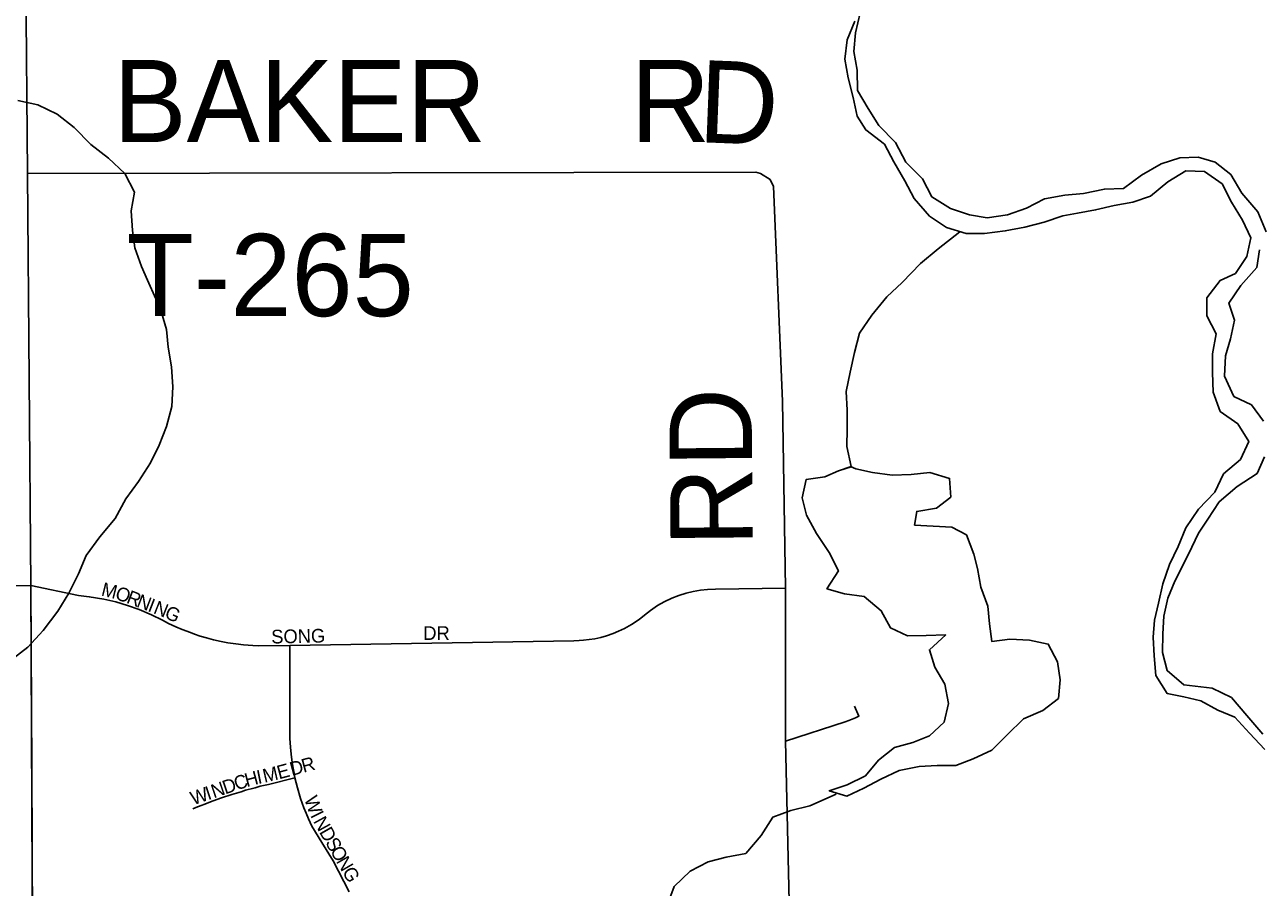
# Model space of a CAD drawing. Extents: x 1985906 to 2277390, y 930619 to 1324581.
# Drawn here: x 2139705 to 2144205, y 1158270 to 1161418 of the extents above; entities that cross this region are included whole.
import ezdxf

# ---------------------------------------------------------------- set-up
doc = ezdxf.new("R2010")
doc.units = 0
for name, color, linetype in [('GM_X_County_Road', 7, 'Continuous'), ('GM_X_Major_River', 7, 'Continuous'), ('GM_X_Minor_Lake', 7, 'Continuous'), ('GM_X_Minor_River', 7, 'Continuous'), ('GM_X_Township', 7, 'Continuous'), ('GM_X_Township_Road', 7, 'Continuous'), ('GM_X_Township_Road_Text', 7, 'Continuous'), ('GM_X_Township_Subdivision', 7, 'Continuous'), ('GM_X_Township_Subdivision_Text', 7, 'Continuous')]:
    doc.layers.add(name, color=color, linetype=linetype)

msp = doc.modelspace()

# ---------------------------------------------------------------- linework, layer by layer
at = {"layer": 'GM_X_County_Road'}
for points in [[(2139728.2, 1159371.8), (2139715.7, 1160875.4), (2139697.8, 1163007), (2139679.7, 1165170.7)], [(2139731.2, 1158704.9), (2139728.2, 1159371.8)], [(2139737.6, 1157268.3), (2139731.2, 1158704.9)]]:
    msp.add_lwpolyline(points, dxfattribs=at)
at = {"layer": 'GM_X_Major_River'}
for points in [[(2144233.2, 1160662.6), (2144203.2, 1160734.7), (2144145.1, 1160802.8), (2144105.1, 1160870.9), (2144047, 1160916.9), (2143985.1, 1160934.9), (2143919.1, 1160932.8), (2143851.1, 1160910.7), (2143779.2, 1160868.6), (2143713.3, 1160820.4), (2143643.3, 1160818.4), (2143567.3, 1160802.3), (2143499.4, 1160796.2), (2143425.4, 1160782.1), (2143359.5, 1160748), (2143289.5, 1160723.9), (2143215.6, 1160713.8), (2143151.6, 1160723.7), (2143081.6, 1160747.7), (2143013.6, 1160789.7), (2142979.5, 1160855.8), (2142919.5, 1160915.9), (2142881.4, 1160988), (2142821.4, 1161050), (2142781.4, 1161112.1), (2142743.3, 1161178.2), (2142741.2, 1161252.3), (2142729.2, 1161320.4), (2142735.1, 1161388.6), (2142753, 1161460.7)], [(2142733.1, 1161430.6), (2142705.1, 1161362.5), (2142697.2, 1161292.4), (2142709.3, 1161224.2), (2142727.3, 1161152.1), (2142741.4, 1161084), (2142773.4, 1161034), (2142841.5, 1160981.9), (2142875.5, 1160917.8), (2142915.6, 1160847.7), (2142949.6, 1160783.6), (2143005.7, 1160719.6), (2143067.7, 1160677.6), (2143139.7, 1160655.6), (2143205.6, 1160655.6), (2143281.6, 1160665.7), (2143353.5, 1160679.8), (2143423.5, 1160697.9), (2143491.5, 1160720), (2143545.4, 1160730.1), (2143611.4, 1160742.2), (2143679.3, 1160758.3), (2143747.3, 1160770.4), (2143811.3, 1160792.5), (2143875.2, 1160844.6), (2143941.1, 1160884.8), (2144009.1, 1160882.8), (2144073.1, 1160836.8), (2144107.2, 1160770.7), (2144147.2, 1160704.6), (2144177.3, 1160640.5), (2144163.3, 1160572.4), (2144121.4, 1160510.2), (2144065.5, 1160484.1), (2144017.5, 1160422), (2144017.6, 1160355.8), (2144051.6, 1160289.8), (2144037.7, 1160217.6), (2144037.8, 1160149.5), (2144039.9, 1160077.3), (2144065.9, 1160007.2), (2144129.9, 1159961.2), (2144170, 1159897.1), (2144140, 1159831)], [(2142733.1, 1161430.6), (2142705.1, 1161362.5), (2142697.2, 1161292.4), (2142709.3, 1161224.2), (2142727.3, 1161152.1), (2142741.4, 1161084), (2142773.4, 1161034), (2142841.5, 1160981.9), (2142875.5, 1160917.8), (2142915.6, 1160847.7), (2142949.6, 1160783.6), (2143005.7, 1160719.6), (2143067.7, 1160677.6), (2143139.7, 1160655.6), (2143205.6, 1160655.6), (2143281.6, 1160665.7), (2143353.5, 1160679.8), (2143423.5, 1160697.9), (2143491.5, 1160720), (2143545.4, 1160730.1), (2143611.4, 1160742.2), (2143679.3, 1160758.3), (2143747.3, 1160770.4), (2143811.3, 1160792.5), (2143875.2, 1160844.6), (2143941.1, 1160884.8), (2144009.1, 1160882.8), (2144073.1, 1160836.8), (2144107.2, 1160770.7), (2144147.2, 1160704.6), (2144177.3, 1160640.5), (2144163.3, 1160572.4), (2144121.4, 1160510.2), (2144065.5, 1160484.1), (2144017.5, 1160422), (2144017.6, 1160355.8), (2144051.6, 1160289.8), (2144037.7, 1160217.6), (2144037.8, 1160149.5), (2144039.9, 1160077.3), (2144065.9, 1160007.2), (2144129.9, 1159961.2), (2144170, 1159897.1), (2144140, 1159831)], [(2144223.9, 1159971.3), (2144179.8, 1160031.4), (2144115.8, 1160061.4), (2144081.8, 1160135.5), (2144085.7, 1160209.6), (2144103.6, 1160271.8), (2144117.6, 1160339.9), (2144097.5, 1160402), (2144141.4, 1160466.1), (2144199.4, 1160532.3), (2144209.3, 1160596.5)], [(2144140, 1159831), (2144078.1, 1159778.8), (2144046.2, 1159712.6), (2143986.3, 1159650.5), (2143940.4, 1159582.3), (2143912.4, 1159514.1), (2143880.5, 1159448), (2143856.6, 1159377.8), (2143840.7, 1159307.7), (2143826.7, 1159245.6), (2143820.8, 1159183.4), (2143824.8, 1159115.3), (2143830.9, 1159043.2), (2143873, 1158977.1), (2143933, 1158965.1), (2143994.9, 1158951.1), (2144056.9, 1158917.1), (2144118.9, 1158891.1), (2144173, 1158833.1), (2144229, 1158773)], [(2144221, 1158829.1), (2144162.9, 1158897.2), (2144106.9, 1158963.3), (2144036.9, 1158997.3), (2143932.9, 1159009.2), (2143872.9, 1159061.2), (2143854.8, 1159127.4), (2143856.8, 1159195.5), (2143860.7, 1159259.6), (2143874.6, 1159325.8), (2143900.6, 1159387.9), (2143932.5, 1159450.1), (2143962.4, 1159512.2), (2143986.4, 1159562.3), (2144020.3, 1159614.4), (2144062.2, 1159676.6), (2144128.1, 1159732.8), (2144200.1, 1159780.9), (2144228, 1159841.1)]]:
    msp.add_lwpolyline(points, dxfattribs=at)
at = {"layer": 'GM_X_Minor_Lake'}
for points in [[(2142720.1, 1159805.4), (2142674.3, 1159789.8), (2142623.4, 1159768.3), (2142555.5, 1159758.3), (2142541.5, 1159692.2), (2142557.5, 1159628.1), (2142593.5, 1159562), (2142639.5, 1159491.9), (2142673.5, 1159425.8), (2142631.6, 1159359.7), (2142695.5, 1159341.7), (2142767.4, 1159331.7), (2142829.4, 1159279.7), (2142863.3, 1159217.6), (2142925.3, 1159187.6), (2142993.2, 1159189.6), (2143065.1, 1159191.7), (2143005.2, 1159137.6), (2143025.2, 1159073.5), (2143061.2, 1159011.4), (2143075.2, 1158941.3), (2143059.2, 1158873.2), (2143005.3, 1158823.1), (2142945.4, 1158799), (2142877.5, 1158780.9), (2142819.6, 1158734.8), (2142771.7, 1158676.7), (2142705.8, 1158644.6), (2142639.9, 1158622.6), (2142703.8, 1158602.6), (2142765.7, 1158632.6), (2142827.6, 1158664.7)], [(2142719.7, 1159805.3), (2142674.3, 1159789.8), (2142623.4, 1159768.3), (2142555.5, 1159758.3), (2142541.5, 1159692.2), (2142557.5, 1159628.1), (2142593.5, 1159562), (2142639.5, 1159491.9), (2142673.5, 1159425.8), (2142631.6, 1159359.7), (2142695.5, 1159341.7), (2142767.4, 1159331.7), (2142829.4, 1159279.7), (2142863.3, 1159217.6), (2142925.3, 1159187.6), (2142993.2, 1159189.6), (2143065.1, 1159191.7), (2143005.2, 1159137.6), (2143025.2, 1159073.5), (2143061.2, 1159011.4), (2143075.2, 1158941.3), (2143059.2, 1158873.2), (2143005.3, 1158823.1), (2142945.4, 1158799), (2142877.5, 1158780.9), (2142819.6, 1158734.8), (2142771.7, 1158676.7), (2142705.8, 1158644.6), (2142639.9, 1158622.6), (2142703.8, 1158602.6), (2142765.7, 1158632.6), (2142827.6, 1158664.7)], [(2142827.6, 1158664.7), (2142895.5, 1158696.8), (2142967.4, 1158710.9), (2143033.3, 1158714.9), (2143101.2, 1158714.9), (2143165.1, 1158739), (2143233, 1158771.1), (2143288.9, 1158827.2), (2143348.8, 1158885.3), (2143418.7, 1158915.4), (2143476.6, 1158959.5), (2143482.6, 1159027.6), (2143472.6, 1159093.7), (2143438.6, 1159157.8), (2143370.7, 1159171.8), (2143298.8, 1159175.8), (2143232.9, 1159167.7), (2143224.9, 1159231.8), (2143218.8, 1159295.9), (2143192.8, 1159366), (2143180.8, 1159434.1), (2143166.8, 1159486.2), (2143140.8, 1159556.3), (2143086.9, 1159584.3), (2142951.1, 1159592.2), (2142959, 1159642.3), (2143030.9, 1159654.4), (2143082.8, 1159694.5), (2143078.8, 1159762.6), (2143006.9, 1159784.6), (2142939, 1159776.5), (2142869.1, 1159774.5), (2142797.2, 1159784.4), (2142736.4, 1159796.9), (2142717.3, 1159806.5)], [(2142827.6, 1158664.7), (2142895.5, 1158696.8), (2142967.4, 1158710.9), (2143033.3, 1158714.9), (2143101.2, 1158714.9), (2143165.1, 1158739), (2143233, 1158771.1), (2143288.9, 1158827.2), (2143348.8, 1158885.3), (2143418.7, 1158915.4), (2143476.6, 1158959.5), (2143482.6, 1159027.6), (2143472.6, 1159093.7), (2143438.6, 1159157.8), (2143370.7, 1159171.8), (2143298.8, 1159175.8), (2143232.9, 1159167.7), (2143224.9, 1159231.8), (2143218.8, 1159295.9), (2143192.8, 1159366), (2143180.8, 1159434.1), (2143166.8, 1159486.2), (2143140.8, 1159556.3), (2143086.9, 1159584.3), (2142951.1, 1159592.2), (2142959, 1159642.3), (2143030.9, 1159654.4), (2143082.8, 1159694.5), (2143078.8, 1159762.6), (2143006.9, 1159784.6), (2142939, 1159776.5), (2142869.1, 1159774.5), (2142797.2, 1159784.4), (2142736.4, 1159796.9), (2142719.7, 1159805.3)]]:
    msp.add_lwpolyline(points, dxfattribs=at)
at = {"layer": 'GM_X_Minor_River'}
for points in [[(2140120.8, 1159750.9), (2140164.6, 1159819.4), (2140196.4, 1159883.7), (2140222.2, 1159952.1), (2140241.9, 1160024.5), (2140245.5, 1160096.8), (2140241.2, 1160169.1), (2140228.8, 1160241.3), (2140222.5, 1160305.5), (2140204.1, 1160367.7), (2140183.8, 1160417.8), (2140153.4, 1160486), (2140131.1, 1160536.1), (2140106.7, 1160604.3), (2140098.4, 1160666.5), (2140094, 1160738.8), (2140105.7, 1160807.1), (2140071.3, 1160875.3), (2140010.9, 1160931.3), (2139946.4, 1160981.3), (2139886, 1161043.3), (2139823.6, 1161091.2), (2139753.2, 1161125.1), (2139680.9, 1161140.9)], [(2143116.2, 1160662.6), (2143037.2, 1160600), (2142972.6, 1160546.4), (2142906.3, 1160476.8), (2142849.6, 1160425.4), (2142795.2, 1160358), (2142750.8, 1160292.9), (2142732.4, 1160222.4), (2142716.1, 1160149.9), (2142701.8, 1160079.4), (2142705.4, 1160011.4), (2142704.9, 1159943.3), (2142704.4, 1159879.2), (2142720.1, 1159805.4)], [(2139652.6, 1159096.6), (2139716.5, 1159147), (2139772.4, 1159207.4), (2139826.2, 1159277.9), (2139866, 1159344.3), (2139901.8, 1159414.8), (2139929.6, 1159481.1), (2139979.4, 1159549.6), (2140035.2, 1159616.1), (2140075, 1159688.5), (2140120.8, 1159750.9)], [(2142664.6, 1158610.7), (2142568.9, 1158567.8), (2142499.4, 1158550.2), (2142434.1, 1158526.7), (2142391.7, 1158459.6), (2142335.3, 1158394.2), (2142263.7, 1158380.5), (2142198.2, 1158362.9), (2142133.1, 1158329.4), (2142074.5, 1158273.9), (2142050, 1158207.2), (2142069.7, 1158135.6), (2142061.3, 1158067.3), (2142050.9, 1157996.9), (2142040.4, 1157932.6), (2142002.1, 1157859.6), (2141973.7, 1157792.8), (2141955.4, 1157722.2), (2141915.1, 1157649.2), (2141878.8, 1157580.2)]]:
    msp.add_lwpolyline(points, dxfattribs=at)
at = {"layer": 'GM_X_Township'}
for points in [[(2139697.8, 1163007), (2139715.7, 1160875.4), (2139728.2, 1159371.8), (2139745, 1155626.5), (2139750.2, 1155246.4), (2139750.9, 1155195.2), (2139750.9, 1154891.9), (2139742.2, 1154437.3), (2139748.3, 1153597.6), (2139771.2, 1150428.8), (2139767.6, 1149880.1), (2139763.4, 1149243.6), (2139772.8, 1148379.5), (2139785.2, 1144742.9), (2139790.1, 1144132.9), (2139795.7, 1143054.9), (2135286.4, 1142976.3)], [(2139771.2, 1150428.8), (2139748.3, 1153597.6), (2139742.2, 1154437.3), (2139750.9, 1154891.9), (2139750.9, 1155195.2), (2139750.2, 1155246.4), (2139745, 1155626.5), (2139728.2, 1159371.8), (2139715.7, 1160875.4), (2139697.8, 1163007)]]:
    msp.add_lwpolyline(points, dxfattribs=at)
at = {"layer": 'GM_X_Township_Road'}
for points in [[(2139715.7, 1160875.4), (2142372.7, 1160879.4), (2142388.7, 1160875.4), (2142424.8, 1160853.5)], [(2142519, 1155650.8), (2142504.6, 1157589.9), (2142495.8, 1158112.1), (2142480.6, 1158803.9), (2142480.6, 1159362.4), (2142469.9, 1160043.8), (2142436.9, 1160827.4), (2142424.8, 1160853.5)], [(2136069.9, 1159324.9), (2137151.4, 1159332.9), (2138108.1, 1159344.7), (2139068.7, 1159359.1), (2139728.2, 1159371.8)]]:
    msp.add_lwpolyline(points, dxfattribs=at)
at = {"layer": 'GM_X_Township_Subdivision'}
for points in [[(2139728.2, 1159371.8), (2139902.2, 1159335.1), (2139941, 1159330.8), (2139994.6, 1159321.7), (2140037.4, 1159311.7), (2140080.5, 1159299.1), (2140123.5, 1159283.7), (2140168.5, 1159264.6), (2140207.8, 1159245.3), (2140230.6, 1159233.5), (2140256.8, 1159221.2), (2140279.3, 1159211.5), (2140309.8, 1159199.7), (2140325.2, 1159194.2), (2140345.9, 1159187.4), (2140369, 1159180.6), (2140394.6, 1159173.9), (2140422.4, 1159167.6), (2140445.9, 1159163.1), (2140475.3, 1159158.5), (2140503.3, 1159155.2), (2140538, 1159152.4), (2140559.8, 1159151.4), (2140672.4, 1159152.5), (2141708.7, 1159170.4), (2141727.9, 1159170.8), (2141744.1, 1159171.9), (2141764.9, 1159174.3), (2141785.1, 1159177.6), (2141806.5, 1159182.4), (2141827.5, 1159188.3), (2141851.9, 1159196.7), (2141871.9, 1159205), (2141892.8, 1159215), (2141918.8, 1159229.7), (2141946.4, 1159248.3), (2141966.3, 1159264), (2141987.8, 1159280.9), (2142013.8, 1159298.3), (2142037.7, 1159312), (2142066.1, 1159325.5), (2142091.3, 1159335.4), (2142117.5, 1159343.6), (2142143.7, 1159349.9), (2142170.8, 1159354.5), (2142195.6, 1159357.1), (2142224.9, 1159358), (2142480.6, 1159362.4)], [(2140888.9, 1158253.8), (2140830.6, 1158367.5), (2140789.4, 1158433.8), (2140753.4, 1158493.1), (2140746.9, 1158506.6), (2140740.8, 1158520.1), (2140732.1, 1158540.5), (2140724.1, 1158560.9), (2140712, 1158595.1), (2140700.6, 1158633.1), (2140691.3, 1158670.4), (2140687.8, 1158687.1), (2140683.4, 1158711), (2140679.7, 1158735.1), (2140677, 1158756.8), (2140674.7, 1158781.4), (2140672.9, 1158814), (2140672.3, 1158851.5), (2140672.4, 1159152.5)], [(2142480.6, 1158803.9), (2142698.4, 1158874.7), (2142711.1, 1158879.1), (2142723.1, 1158883.7), (2142735.1, 1158888.8), (2142748.4, 1158895), (2142731.5, 1158931.2)], [(2140318.3, 1158556.6), (2140336.4, 1158564), (2140353, 1158570.6), (2140358.5, 1158572.8), (2140393.2, 1158585.8), (2140423.7, 1158596.7), (2140460.8, 1158609), (2140494.6, 1158619.5), (2140511.2, 1158624.4), (2140520.3, 1158626.9), (2140532, 1158630.2), (2140545.9, 1158634), (2140564.8, 1158639), (2140594.2, 1158646.2), (2140691.3, 1158670.4)]]:
    msp.add_lwpolyline(points, dxfattribs=at)

# ---------------------------------------------------------------- texts
at = {"layer": 'GM_X_Township_Road_Text'}
for s, rotation, p in [('BAKER', 0, (2140028.5, 1160989.5)), ('R', 359.9844, (2141916.1, 1160989.5)), ('D', 357.7883, (2142159.4, 1160989.5)), ('T-265', 0, (2140076.9, 1160354.6)), ('RD', 90.4937, (2142361.3, 1159514.6))]:
    msp.add_text(s, height=300, rotation=rotation, dxfattribs=at).set_placement(p)
at = {"layer": 'GM_X_Township_Subdivision_Text'}
for s, rotation, p in [('M', 346.2641, (2139982, 1159335.7)), ('O', 341.1297, (2140032.2, 1159323.5)), ('R', 339.0148, (2140073.4, 1159309.4)), ('N', 338.917, (2140110.3, 1159295.2)), ('I', 338.9179, (2140151.4, 1159279.4)), ('N', 338.3772, (2140171.8, 1159271.5)), ('G', 335.8888, (2140212.2, 1159255.5)), ('SONG', 1.1677, (2140605.2, 1159159.9)), ('DR', 0, (2141159.3, 1159173.1)), ('R', 15.0012, (2140722.4, 1158688.1)), ('H', 15.0328, (2140515.1, 1158635.9)), ('I', 11.3957, (2140556.8, 1158647.1)), ('M', 13.0779, (2140579.9, 1158651.8)), ('E', 14.9619, (2140633.1, 1158664.2)), ('D', 15.0117, (2140679.9, 1158676.7)), ('N', 18.7391, (2140395.1, 1158595.1)), ('D', 18.7321, (2140436.8, 1158609.3)), ('C', 18.7382, (2140478.4, 1158623.4)), ('W', 18.7274, (2140320.1, 1158569.7)), ('I', 18.7476, (2140374.3, 1158588.1)), ('W', 289.5464, (2140724.2, 1158593.5)), ('I', 296.4666, (2140745.9, 1158533.5)), ('N', 298.7982, (2140756.7, 1158511.8)), ('D', 299.864, (2140778.4, 1158472.4)), ('S', 299.9806, (2140800.4, 1158434.2)), ('O', 299.978, (2140818, 1158403.7)), ('N', 299.978, (2140839.9, 1158365.5)), ('G', 299.978, (2140861.9, 1158327.4))]:
    msp.add_text(s, height=50, rotation=rotation, dxfattribs=at).set_placement(p)

doc.saveas('drawing.dxf')
